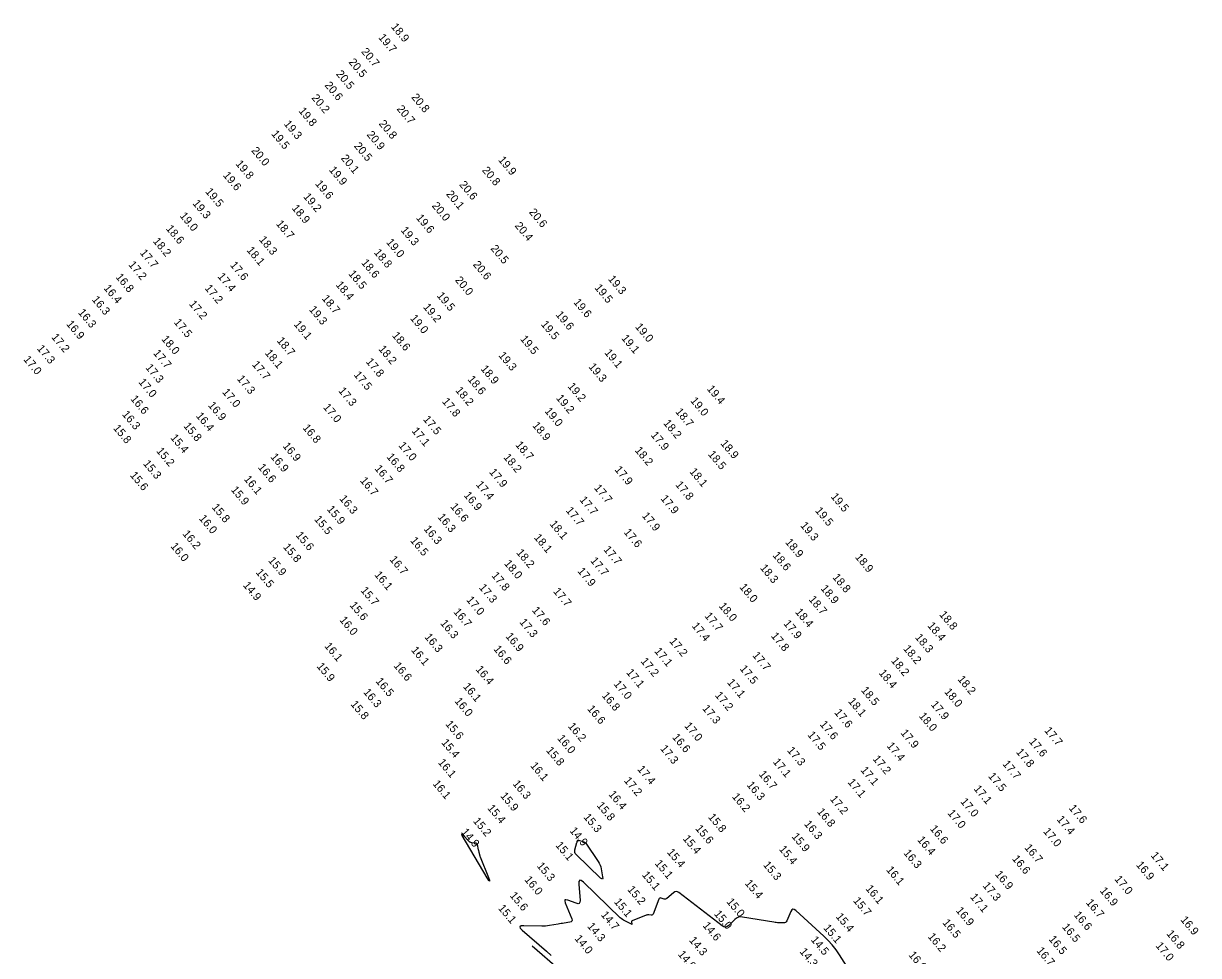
# Model space of a CAD drawing. Extents: x 988130 to 1132882, y 654656 to 841453.
# Drawn here: x 1108310 to 1109044, y 682759 to 683341 of the extents above; entities that cross this region are included whole.
import ezdxf

# ---------------------------------------------------------------- set-up
doc = ezdxf.new("R2010")
doc.units = 0
doc.layers.add('V-TOPO-MAJR', color=7, linetype='Continuous')
doc.layers.add('V-TOPO-SOUN', color=7, linetype='Continuous')

msp = doc.modelspace()

# ---------------------------------------------------------------- linework, layer by layer
at = {"layer": 'V-TOPO-MAJR'}
for points in [[(1108583.88, 682834.67), (1108584.15, 682834.53), (1108584.76, 682833.96), (1108588.71, 682829.9), (1108589.08, 682829.58), (1108589.48, 682829.35), (1108589.91, 682829.2), (1108590.39, 682829.13), (1108592.36, 682829.02), (1108592.81, 682828.93), (1108593.16, 682828.73), (1108593.41, 682828.42), (1108593.57, 682827.99), (1108594.31, 682824.72), (1108594.4, 682824.35), (1108594.49, 682823.97), (1108594.57, 682823.6), (1108594.67, 682823.23), (1108595.04, 682821.75), (1108595.14, 682821.38), (1108595.25, 682821.02), (1108595.37, 682820.66), (1108595.5, 682820.3), (1108600.62, 682807.41), (1108601.25, 682805.69), (1108601.35, 682805.06), (1108600.92, 682805.52), (1108599.95, 682807.08), (1108584.33, 682833.63), (1108583.94, 682834.37)], [(1108656.08, 682829.55), (1108656.14, 682829.72), (1108656.2, 682829.88), (1108656.45, 682830.52), (1108656.52, 682830.66), (1108656.63, 682830.74), (1108656.75, 682830.77), (1108656.9, 682830.75), (1108659.73, 682829.9), (1108660.23, 682829.71), (1108660.68, 682829.44), (1108661.07, 682829.09), (1108661.41, 682828.68), (1108669.21, 682817.32), (1108669.86, 682816.25), (1108670.4, 682815.13), (1108670.81, 682813.96), (1108671.1, 682812.74), (1108672.02, 682807.75), (1108672.1, 682806.77), (1108671.9, 682806.32), (1108671.42, 682806.41), (1108670.65, 682807.02), (1108655.44, 682821.71), (1108654.92, 682822.34), (1108654.62, 682823.03), (1108654.54, 682823.77), (1108654.67, 682824.57), (1108655.98, 682829.22), (1108656.03, 682829.39)]]:
    msp.add_lwpolyline(points, close=True, dxfattribs=at)
for points in [[(1108830.52, 682742.33), (1108820.02, 682758.95), (1108817.84, 682762.16), (1108815.46, 682765.2), (1108812.88, 682768.08), (1108810.11, 682770.8), (1108792.64, 682786.8), (1108791.72, 682787.43), (1108790.91, 682787.54), (1108790.21, 682787.12), (1108789.62, 682786.18), (1108787, 682780.29), (1108786.65, 682779.7), (1108786.18, 682779.29), (1108785.61, 682779.05), (1108784.93, 682778.99), (1108781.99, 682779.07), (1108781.25, 682779.1), (1108780.52, 682779.16), (1108779.79, 682779.24), (1108779.06, 682779.35), (1108759.31, 682782.65), (1108758.02, 682782.73), (1108756.81, 682782.51), (1108755.7, 682782.01), (1108754.68, 682781.2), (1108750.78, 682777.42), (1108749.79, 682776.69), (1108748.78, 682776.41), (1108747.74, 682776.57), (1108746.67, 682777.17), (1108719.52, 682797.96), (1108718.68, 682798.44), (1108717.85, 682798.58), (1108717.03, 682798.38), (1108716.22, 682797.84), (1108712.18, 682794.23), (1108711.78, 682793.95), (1108711.36, 682793.79), (1108710.91, 682793.76), (1108710.43, 682793.85), (1108708.48, 682794.46), (1108708.03, 682794.54), (1108707.66, 682794.45), (1108707.36, 682794.21), (1108707.14, 682793.81), (1108703.55, 682784.5), (1108703.37, 682784.17), (1108703.12, 682783.94), (1108702.81, 682783.82), (1108702.43, 682783.81), (1108700.78, 682783.96), (1108700.37, 682783.97), (1108699.97, 682783.94), (1108699.57, 682783.86), (1108699.18, 682783.73), (1108690.48, 682780.29), (1108690.26, 682780.16), (1108690.12, 682780), (1108690.06, 682779.79), (1108690.09, 682779.54), (1108690.34, 682778.46), (1108690.37, 682778.23), (1108690.32, 682778.11), (1108690.18, 682778.09), (1108689.97, 682778.16), (1108685.84, 682780.25), (1108685.08, 682780.67), (1108684.37, 682781.14), (1108683.69, 682781.66), (1108683.04, 682782.23), (1108659.98, 682804.5), (1108658.64, 682805.55), (1108657.73, 682805.68), (1108657.24, 682804.89), (1108657.19, 682803.19), (1108657.94, 682793.05), (1108657.86, 682791.88), (1108657.43, 682791.19), (1108656.64, 682790.97), (1108655.5, 682791.23), (1108650.21, 682793.21), (1108649.12, 682793.48), (1108648.49, 682793.3), (1108648.33, 682792.67), (1108648.63, 682791.59), (1108652.74, 682781.53), (1108652.94, 682780.75), (1108652.81, 682780.15), (1108652.37, 682779.72), (1108651.6, 682779.47), (1108647.9, 682778.83), (1108646.98, 682778.68), (1108646.05, 682778.52), (1108645.12, 682778.36), (1108644.2, 682778.21), (1108638.82, 682777.31), (1108637.61, 682777.14), (1108636.4, 682777.03), (1108635.18, 682776.97), (1108633.96, 682776.97), (1108622.82, 682777.24), (1108621.05, 682777.1), (1108620.28, 682776.58), (1108620.5, 682775.67), (1108621.71, 682774.38), (1108636.86, 682761.26), (1108639.95, 682758.56)], [(1108645.37, 682749.45), (1108628.06, 682764.38)]]:
    msp.add_lwpolyline(points, dxfattribs=at)

# ---------------------------------------------------------------- texts
at = {"layer": 'V-TOPO-SOUN'}
for s, p in [('18.9 ', (1108539.53, 683338.49)), ('19.7 ', (1108531.64, 683331.81)), ('20.7 ', (1108520.92, 683322.98)), ('20.5 ', (1108513.05, 683316.44)), ('20.5 ', (1108505.19, 683309.05)), ('20.6 ', (1108498.06, 683302)), ('20.2 ', (1108489.88, 683294.1)), ('20.8 ', (1108552.24, 683294.51)), ('19.8 ', (1108481.81, 683285.92)), ('20.7 ', (1108543.08, 683287.24)), ('19.3 ', (1108472.58, 683277.84)), ('20.8 ', (1108531.89, 683277.98)), ('19.5 ', (1108464.76, 683271.6)), ('20.9 ', (1108524.37, 683271.16)), ('20.0 ', (1108452.25, 683261.2)), ('20.5 ', (1108516.42, 683264.09)), ('19.8 ', (1108442.41, 683252.91)), ('20.1 ', (1108508.24, 683256.43)), ('19.9 ', (1108606.52, 683255.33)), ('19.6 ', (1108434.57, 683245.75)), ('19.9 ', (1108500.78, 683249.09)), ('20.8 ', (1108596.43, 683248.88)), ('19.6 ', (1108492.14, 683240.44)), ('20.6 ', (1108582.15, 683239.93)), ('19.5 ', (1108423.5, 683235.54)), ('19.2 ', (1108484.74, 683232.39)), ('20.1 ', (1108573.94, 683233.98)), ('19.3 ', (1108415.55, 683228.2)), ('18.9 ', (1108477.54, 683225.22)), ('20.0 ', (1108565.05, 683226.73)), ('20.6 ', (1108625.71, 683222.74)), ('19.0 ', (1108407.54, 683220.42)), ('18.7 ', (1108467.66, 683215.46)), ('19.6 ', (1108555.19, 683219.14)), ('20.4 ', (1108616.85, 683214.26)), ('18.6 ', (1108398.91, 683212.42)), ('19.3 ', (1108545.6, 683211.44)), ('18.2 ', (1108390.79, 683204.59)), ('18.3 ', (1108457.06, 683205.56)), ('19.0 ', (1108536.54, 683203.91)), ('20.5 ', (1108601.72, 683200.03)), ('17.7 ', (1108382.64, 683197.3)), ('18.1 ', (1108449.34, 683198.96)), ('18.8 ', (1108528.84, 683197.52)), ('17.2 ', (1108375.49, 683189.92)), ('17.6 ', (1108438.97, 683189.67)), ('18.6 ', (1108520.95, 683191.15)), ('20.6 ', (1108590.71, 683190.03)), ('16.8 ', (1108367.5, 683182.19)), ('17.4 ', (1108431.16, 683182.58)), ('18.5 ', (1108512.92, 683184.22)), ('20.0 ', (1108579.52, 683180.3)), ('19.3 ', (1108675.12, 683180.97)), ('16.4 ', (1108359.99, 683175.28)), ('17.2 ', (1108423.15, 683175.24)), ('18.4 ', (1108504.99, 683177.35)), ('19.5 ', (1108568.15, 683170.56)), ('19.5 ', (1108666.69, 683175.53)), ('16.3 ', (1108352.64, 683168.12)), ('17.2 ', (1108413.35, 683165.37)), ('18.7 ', (1108496.31, 683168.8)), ('19.2 ', (1108559.61, 683163.46)), ('19.6 ', (1108653.51, 683166.45)), ('16.3 ', (1108344, 683160.04)), ('19.3 ', (1108488.31, 683161.94)), ('19.0 ', (1108551.47, 683156.45)), ('19.6 ', (1108642.4, 683158.69)), ('16.9 ', (1108336.65, 683152.85)), ('17.5 ', (1108403.88, 683153.96)), ('19.1 ', (1108478.79, 683152.68)), ('19.5 ', (1108633.21, 683152.67)), ('19.0 ', (1108692.05, 683151.11)), ('17.2 ', (1108327.33, 683144.67)), ('18.0 ', (1108396.08, 683143.44)), ('18.7 ', (1108468.19, 683142.44)), ('18.6 ', (1108540.18, 683145.7)), ('19.5 ', (1108620.26, 683143.5)), ('19.1 ', (1108683.46, 683144)), ('17.3 ', (1108318.29, 683137.57)), ('17.7 ', (1108390.96, 683134.67)), ('18.1 ', (1108460.73, 683134.73)), ('18.2 ', (1108531.69, 683137.25)), ('19.1 ', (1108672.87, 683134.94)), ('17.0 ', (1108309.87, 683130.77)), ('17.7 ', (1108452.68, 683127.55)), ('17.8 ', (1108523.82, 683129.32)), ('19.3 ', (1108606.65, 683133.25)), ('17.3 ', (1108386.13, 683125.66)), ('17.5 ', (1108516.28, 683121.14)), ('18.9 ', (1108595.53, 683124.87)), ('19.3 ', (1108662.93, 683126.19)), ('17.0 ', (1108381.75, 683116.58)), ('17.3 ', (1108443.29, 683118.64)), ('18.6 ', (1108587.39, 683118.32)), ('19.2 ', (1108649.9, 683113.94)), ('19.4 ', (1108736.88, 683112.36)), ('16.6 ', (1108376.78, 683106.1)), ('17.0 ', (1108434.07, 683110.34)), ('17.3 ', (1108506.67, 683111.15)), ('17.8 ', (1108571.43, 683104.46)), ('18.2 ', (1108579.74, 683111.41)), ('19.2 ', (1108642.67, 683106.58)), ('19.0 ', (1108726.54, 683104.95)), ('16.9 ', (1108425.22, 683102.08)), ('17.0 ', (1108497.11, 683100.88)), ('19.0 ', (1108635.5, 683098.46)), ('18.7 ', (1108717.16, 683098.1)), ('16.3 ', (1108371.5, 683096.46)), ('16.4 ', (1108417.66, 683095.46)), ('17.5 ', (1108559.57, 683093.32)), ('18.2 ', (1108709.66, 683090.92)), ('15.8 ', (1108365.96, 683087.82)), ('15.8 ', (1108409.9, 683089.15)), ('16.8 ', (1108484.32, 683088.05)), ('17.1 ', (1108552.46, 683086.1)), ('18.9 ', (1108627.81, 683089.52)), ('17.9 ', (1108701.83, 683083.47)), ('15.4 ', (1108401.71, 683081.81)), ('16.9 ', (1108471.86, 683076.67)), ('17.0 ', (1108544.18, 683077)), ('18.7 ', (1108617.22, 683077.4)), ('18.9 ', (1108745.36, 683078.28)), ('15.2 ', (1108392.91, 683073.54)), ('16.9 ', (1108464.22, 683069.9)), ('16.8 ', (1108536.77, 683069.88)), ('18.2 ', (1108609.76, 683069.61)), ('18.2 ', (1108691.85, 683073.96)), ('18.5 ', (1108737.56, 683071.51)), ('15.3 ', (1108384.66, 683065.65)), ('16.6 ', (1108456.38, 683063.37)), ('16.7 ', (1108529.25, 683062.59)), ('17.9 ', (1108600.86, 683060.38)), ('17.9 ', (1108679.22, 683061.92)), ('18.1 ', (1108725.99, 683060.66)), ('15.6 ', (1108376.46, 683058.42)), ('16.1 ', (1108447.63, 683056)), ('16.7 ', (1108520.17, 683055.06)), ('15.9 ', (1108439.51, 683049.34)), ('16.9 ', (1108585.01, 683045.9)), ('17.4 ', (1108592.57, 683052.58)), ('17.7 ', (1108666.37, 683050.47)), ('17.8 ', (1108717.19, 683052.48)), ('15.8 ', (1108427.53, 683038.44)), ('16.3 ', (1108507.28, 683043.8)), ('16.6 ', (1108576.6, 683038.82)), ('17.7 ', (1108657.32, 683043.06)), ('17.9 ', (1108707.95, 683043.83)), ('19.5 ', (1108814.26, 683045.06)), ('16.0 ', (1108419.53, 683031.45)), ('15.5 ', (1108491.53, 683030.96)), ('15.9 ', (1108499.47, 683037.24)), ('16.3 ', (1108568.65, 683032.3)), ('17.7 ', (1108648.73, 683036.39)), ('17.9 ', (1108696.29, 683033.09)), ('19.5 ', (1108804.48, 683036.28)), ('16.3 ', (1108559.97, 683024.88)), ('18.1 ', (1108638.65, 683027.96)), ('19.3 ', (1108795.24, 683027.03)), ('16.2 ', (1108409.26, 683021.84)), ('15.6 ', (1108479.98, 683020.97)), ('16.5 ', (1108551.53, 683017.62)), ('18.1 ', (1108628.83, 683019.51)), ('17.6 ', (1108684.94, 683022.84)), ('18.9 ', (1108785.79, 683016.57)), ('16.0 ', (1108401.78, 683014.1)), ('15.8 ', (1108472.1, 683013.59)), ('18.2 ', (1108617.8, 683010.08)), ('17.7 ', (1108672.27, 683012.02)), ('15.9 ', (1108462.8, 683005.17)), ('16.7 ', (1108538.64, 683005.8)), ('18.0 ', (1108610.19, 683003.29)), ('17.7 ', (1108664.07, 683005.03)), ('18.6 ', (1108777.94, 683008.41)), ('18.9 ', (1108829.46, 683007.28)), ('15.5 ', (1108455.03, 682997.74)), ('16.1 ', (1108529.17, 682996.25)), ('17.8 ', (1108602.32, 682995.77)), ('17.9 ', (1108656.03, 682998.53)), ('18.3 ', (1108770.09, 683000.56)), ('18.8 ', (1108815.33, 682994.68)), ('14.9 ', (1108447.08, 682989.69)), ('17.3 ', (1108594.45, 682988.27)), ('18.0 ', (1108757.2, 682988.54)), ('18.9 ', (1108807.93, 682987.68)), ('15.7 ', (1108520.53, 682986.5)), ('17.0 ', (1108586.58, 682980.58)), ('17.7 ', (1108640.86, 682985.89)), ('18.7 ', (1108800.48, 682980.87)), ('15.6 ', (1108513.69, 682977.25)), ('16.7 ', (1108578.53, 682973.1)), ('17.6 ', (1108627.59, 682974.1)), ('18.0 ', (1108744.34, 682976.72)), ('18.4 ', (1108792.01, 682973)), ('16.0 ', (1108507.36, 682968)), ('16.3 ', (1108570.28, 682965.97)), ('17.3 ', (1108619.76, 682966.67)), ('17.7 ', (1108735.41, 682970.54)), ('17.9 ', (1108784.74, 682965.78)), ('18.8 ', (1108882.05, 682971.4)), ('16.9 ', (1108611.09, 682957.82)), ('17.4 ', (1108727.47, 682964.32)), ('17.8 ', (1108776.91, 682958.05)), ('18.4 ', (1108874.67, 682964.46)), ('16.1 ', (1108497.91, 682951.73)), ('16.3 ', (1108560.48, 682957.38)), ('17.2 ', (1108713.41, 682954.75)), ('18.3 ', (1108866.91, 682957.16)), ('16.1 ', (1108552.09, 682949.22)), ('16.6 ', (1108603.57, 682949.89)), ('17.1 ', (1108704.03, 682948.52)), ('17.7 ', (1108765.28, 682945.93)), ('18.2 ', (1108859.53, 682950.11)), ('15.9 ', (1108493.1, 682939.11)), ('16.6 ', (1108541.16, 682939.46)), ('16.4 ', (1108592.41, 682937.2)), ('17.2 ', (1108695.51, 682942.22)), ('17.5 ', (1108757.39, 682937.58)), ('18.2 ', (1108851.93, 682942.58)), ('16.5 ', (1108529.94, 682929.77)), ('17.1 ', (1108686.5, 682935.23)), ('17.1 ', (1108749.52, 682929)), ('18.4 ', (1108844.26, 682934.91)), ('18.2 ', (1108893.49, 682931.04)), ('16.3 ', (1108522.22, 682922.93)), ('16.1 ', (1108584.52, 682926.47)), ('17.0 ', (1108678.65, 682928.05)), ('17.2 ', (1108741.91, 682920.98)), ('18.5 ', (1108833.17, 682924.15)), ('18.0 ', (1108885.18, 682923.16)), ('15.8 ', (1108514.27, 682915.42)), ('16.0 ', (1108579.24, 682917.36)), ('16.8 ', (1108671.22, 682920.82)), ('18.1 ', (1108825.11, 682917.21)), ('17.9 ', (1108876.78, 682915.22)), ('16.6 ', (1108662.12, 682912.54)), ('17.3 ', (1108733.99, 682912.75)), ('17.6 ', (1108816.48, 682910.21)), ('18.0 ', (1108869.31, 682908.05)), ('15.6 ', (1108573.52, 682902.98)), ('16.2 ', (1108650.07, 682901.67)), ('17.0 ', (1108722.77, 682901.91)), ('17.6 ', (1108807.41, 682902.85)), ('17.7 ', (1108947.68, 682898.98)), ('16.0 ', (1108643.4, 682894.1)), ('16.6 ', (1108715.19, 682894.78)), ('17.5 ', (1108799.74, 682896.28)), ('17.9 ', (1108857.9, 682897.47)), ('17.6 ', (1108938.06, 682892.08)), ('15.4 ', (1108570.99, 682891.45)), ('15.8 ', (1108636.42, 682886.56)), ('17.3 ', (1108707.71, 682887.69)), ('17.3 ', (1108787.01, 682886.55)), ('17.4 ', (1108849.2, 682889.43)), ('17.8 ', (1108930.01, 682885.56)), ('16.1 ', (1108568.88, 682879.03)), ('16.1 ', (1108626.56, 682877.03)), ('17.1 ', (1108778.11, 682879.38)), ('17.2 ', (1108840.49, 682881.25)), ('17.7 ', (1108921.56, 682878.09)), ('17.4 ', (1108693.38, 682874.85)), ('16.7 ', (1108769.28, 682871.72)), ('17.1 ', (1108832.88, 682874.26)), ('17.5 ', (1108912.59, 682870.48)), ('16.1 ', (1108565.53, 682865.74)), ('16.3 ', (1108615.5, 682865.74)), ('17.2 ', (1108685.05, 682867.69)), ('16.3 ', (1108761.77, 682864.98)), ('17.1 ', (1108824.82, 682866.7)), ('17.1 ', (1108903.59, 682862.59)), ('15.9 ', (1108607.83, 682858.17)), ('16.4 ', (1108675.41, 682859.18)), ('16.2 ', (1108752.55, 682857.67)), ('17.2 ', (1108813.75, 682856.17)), ('15.4 ', (1108599.75, 682850.5)), ('15.8 ', (1108668.08, 682852.17)), ('16.8 ', (1108805.68, 682848.28)), ('17.0 ', (1108895.26, 682854.57)), ('17.6 ', (1108962.97, 682850.52)), ('15.2 ', (1108590.77, 682842.45)), ('15.3 ', (1108659.79, 682844.9)), ('15.8 ', (1108737.64, 682844.92)), ('16.3 ', (1108797.59, 682840.6)), ('17.0 ', (1108887.22, 682847.42)), ('17.4 ', (1108955.43, 682843.52)), ('14.9 ', (1108583.39, 682835.62)), ('14.9 ', (1108651.12, 682836.4)), ('15.6 ', (1108729.63, 682837.77)), ('15.9 ', (1108789.81, 682832.77)), ('16.6 ', (1108876.21, 682837.66)), ('17.0 ', (1108946.98, 682835.94)), ('15.1 ', (1108642.27, 682827.3)), ('15.4 ', (1108721.83, 682831.44)), ('16.4 ', (1108868.31, 682830.75)), ('16.7 ', (1108935.27, 682825.82)), ('15.4 ', (1108711.97, 682822.95)), ('15.4 ', (1108781.93, 682824.91)), ('16.3 ', (1108859.74, 682822.48)), ('16.6 ', (1108927.53, 682818.88)), ('17.1 ', (1109014.18, 682820.96)), ('15.3 ', (1108630.62, 682814.46)), ('15.1 ', (1108704.34, 682815.96)), ('15.3 ', (1108772.02, 682815.07)), ('16.1 ', (1108848.88, 682812)), ('16.9 ', (1109005.01, 682815.07)), ('16.0 ', (1108622.89, 682805.85)), ('15.1 ', (1108696.33, 682808.81)), ('15.4 ', (1108760.57, 682803.56)), ('16.9 ', (1108916.85, 682809.21)), ('17.0 ', (1108991.52, 682806.19)), ('15.2 ', (1108687.19, 682799.72)), ('16.1 ', (1108835.99, 682800.24)), ('17.3 ', (1108909.16, 682802.1)), ('16.9 ', (1108982.33, 682798.92)), ('15.6 ', (1108613.72, 682795.93)), ('15.1 ', (1108678.83, 682792)), ('15.0 ', (1108749.13, 682792.04)), ('15.7 ', (1108828.23, 682792.73)), ('17.1 ', (1108901.33, 682795)), ('16.7 ', (1108973.68, 682791.49)), ('15.1 ', (1108606.45, 682788.01)), ('14.7 ', (1108670.67, 682783.89)), ('15.0 ', (1108741.33, 682784.46)), ('15.4 ', (1108817.39, 682782.74)), ('16.9 ', (1108892.4, 682786.55)), ('16.6 ', (1108966.11, 682783.81)), ('14.3 ', (1108662.1, 682776.75)), ('14.6 ', (1108734.24, 682777.2)), ('15.1 ', (1108809.66, 682775.71)), ('16.5 ', (1108884.05, 682778.97)), ('16.5 ', (1108958.76, 682776.3)), ('16.9 ', (1109032.73, 682780.81)), ('14.0 ', (1108654.21, 682769.06)), ('14.3 ', (1108725.72, 682768)), ('14.5 ', (1108801.82, 682768.29)), ('16.2 ', (1108874.87, 682770.28)), ('16.5 ', (1108950.39, 682768.67)), ('16.8 ', (1109023.97, 682772.1)), ('14.3 ', (1108794.79, 682760.9)), ('16.7 ', (1108942.8, 682761.5)), ('17.0 ', (1109017.2, 682764.6)), ('14.0 ', (1108718.76, 682759.24)), ('16.0 ', (1108862.87, 682758.81))]:
    msp.add_text(s, height=5, rotation=310, dxfattribs=at).set_placement(p)

doc.saveas('drawing.dxf')
